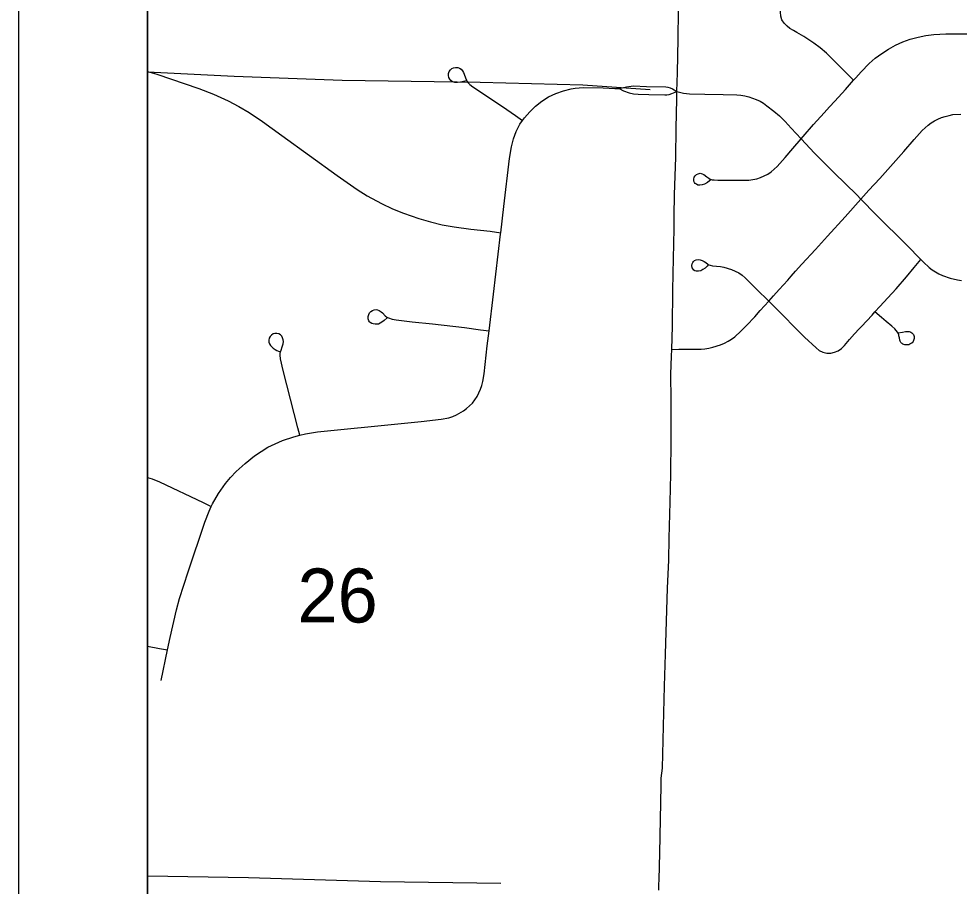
# Model space of a CAD drawing. Extents: x -59 to 43, y 0 to 22.
# Drawn here: x 23.417 to 24.147, y 16.594 to 17.267 of the extents above; entities that cross this region are included whole.
import ezdxf

# ---------------------------------------------------------------- set-up
doc = ezdxf.new("R2010")
doc.units = 0
for name, color, linetype in [('Default', 7, 'Continuous'), ('GM_X_City_Street', 7, 'Continuous'), ('GM_X_Interchange_Ramps', 7, 'Continuous'), ('GM_X_Minor_River', 7, 'Continuous'), ('GM_X_Section_Text', 7, 'Continuous'), ('GM_X_Township_Road', 7, 'Continuous'), ('SH_Data', 7, 'Continuous')]:
    doc.layers.add(name, color=color, linetype=linetype)

msp = doc.modelspace()

# ---------------------------------------------------------------- linework, layer by layer
at = {"layer": 'Default'}
msp.add_lwpolyline([(23.51667, 17.35203), (23.51667, 16.35874), (24.14766, 16.33962), (24.1786, 17.34343), (23.63449, 17.34676)], close=True, dxfattribs=at)
at = {"layer": 'GM_X_City_Street'}
for points in [[(24.0646, 17.21948), (24.05888, 17.22518), (24.04347, 17.24048), (24.03874, 17.24455), (24.03372, 17.24826), (24.02584, 17.25337), (24.02046, 17.25653), (24.01783, 17.25819), (24.01514, 17.25973), (24.01288, 17.26144), (24.01073, 17.26369), (24.00892, 17.26623), (24.008, 17.26917), (24.00777, 17.27228), (24.00828, 17.28166), (24.00876, 17.29728), (24.00945, 17.33483), (24.00959, 17.33796), (24.00997, 17.34632)], [(23.95384, 17.14226), (23.95265, 17.14136), (23.95114, 17.14025), (23.94879, 17.13888), (23.94698, 17.13819), (23.94521, 17.13794), (23.94369, 17.13818), (23.94254, 17.13871), (23.94158, 17.13939), (23.9411, 17.14003), (23.94068, 17.14123), (23.94055, 17.14267), (23.94093, 17.14424), (23.94151, 17.14535), (23.9426, 17.14638), (23.94392, 17.14696), (23.94558, 17.14724), (23.94698, 17.14696), (23.94841, 17.14625), (23.95076, 17.14448), (23.95212, 17.14337), (23.9533, 17.14267), (23.95475, 17.14225), (23.95624, 17.1421), (23.95929, 17.14197), (23.96545, 17.14194), (23.97474, 17.14187), (23.98324, 17.14204), (23.98632, 17.14238), (23.98936, 17.14306), (23.99233, 17.144), (23.9952, 17.1452), (23.99794, 17.14667), (24.00052, 17.1484), (24.0029, 17.15039), (24.00515, 17.15255), (24.01138, 17.1595), (24.01734, 17.16652), (24.0239, 17.17397), (24.02543, 17.1757), (24.03355, 17.18503), (24.04175, 17.19423), (24.04594, 17.19878), (24.0501, 17.20333), (24.05819, 17.21236), (24.0646, 17.21948), (24.06638, 17.22146), (24.07052, 17.22605), (24.0767, 17.23256), (24.07896, 17.23464), (24.08135, 17.23663), (24.08639, 17.24032), (24.09165, 17.24362), (24.09711, 17.24658), (24.10276, 17.24917), (24.10858, 17.25133), (24.11457, 17.25299), (24.12069, 17.25418), (24.12687, 17.25495), (24.13616, 17.25542), (24.1453, 17.25557), (24.15739, 17.25535)], [(23.51667, 17.22635), (23.52379, 17.22406), (23.55627, 17.21303), (23.56784, 17.20854), (23.57913, 17.20339), (23.5874, 17.19913), (23.59541, 17.19442), (23.60573, 17.18754), (23.62086, 17.17658), (23.66385, 17.14561), (23.67916, 17.1348), (23.68713, 17.12984), (23.69811, 17.12382), (23.70659, 17.11978), (23.7153, 17.11624), (23.72713, 17.11213), (23.73615, 17.10951), (23.74531, 17.10741), (23.75457, 17.10583), (23.76755, 17.10403), (23.78237, 17.10226), (23.79066, 17.10114)], [(23.76394, 17.21895), (23.76172, 17.21838), (23.75946, 17.21792), (23.75723, 17.21764), (23.75514, 17.21772), (23.75338, 17.21834), (23.75204, 17.21915), (23.75107, 17.22031), (23.7504, 17.22161), (23.75015, 17.2232), (23.75027, 17.2247), (23.75076, 17.22619), (23.75165, 17.2276), (23.75273, 17.22849), (23.75411, 17.22918), (23.7556, 17.22942), (23.75733, 17.22931), (23.75858, 17.2288), (23.76004, 17.22798), (23.76113, 17.22681), (23.76192, 17.22537), (23.76239, 17.22424), (23.76337, 17.22128), (23.76402, 17.21957), (23.76465, 17.21852), (23.76547, 17.21739), (23.76665, 17.21626), (23.76906, 17.21438), (23.79208, 17.19903), (23.80214, 17.192), (23.80755, 17.18822)], [(23.52713, 16.7537), (23.53214, 16.7774), (23.5342, 16.78719), (23.53894, 16.80845), (23.54143, 16.81744), (23.5482, 16.83814), (23.56092, 16.87655), (23.56433, 16.88523), (23.56602, 16.88874), (23.56703, 16.89083), (23.57176, 16.89887), (23.57713, 16.90651), (23.58108, 16.91133), (23.58535, 16.91586), (23.59222, 16.92217), (23.59953, 16.92797), (23.60467, 16.93149), (23.61002, 16.93466), (23.61559, 16.93744), (23.62133, 16.93985), (23.63016, 16.94286), (23.63472, 16.944), (23.63921, 16.94512), (23.64841, 16.9467), (23.66389, 16.94829), (23.69795, 16.9517), (23.72893, 16.95465), (23.7444, 16.95641), (23.7505, 16.95762), (23.75345, 16.95858), (23.75629, 16.95984), (23.76172, 16.96289), (23.76424, 16.96471), (23.76658, 16.96676), (23.76873, 16.96902), (23.77065, 16.97146), (23.77234, 16.97407), (23.7738, 16.97682), (23.77501, 16.97968), (23.77599, 16.98264), (23.77675, 16.98565), (23.77778, 16.99179), (23.78025, 17.01343), (23.7816, 17.02497), (23.78498, 17.05361), (23.79052, 17.09996), (23.79066, 17.10114), (23.79317, 17.12158), (23.79753, 17.15867), (23.79904, 17.16788), (23.80058, 17.17391), (23.8028, 17.17973), (23.80562, 17.18527), (23.80755, 17.18822), (23.80916, 17.19037), (23.81324, 17.19507), (23.81769, 17.19942), (23.8226, 17.20325), (23.82787, 17.20655), (23.83348, 17.20925), (23.83935, 17.21132), (23.84538, 17.21285), (23.84845, 17.21334), (23.85466, 17.21374), (23.87021, 17.21349), (23.87922, 17.2131), (23.88265, 17.21295)], [(23.88265, 17.21295), (23.88823, 17.21437), (23.89382, 17.21503), (23.90384, 17.21472), (23.91889, 17.21424), (23.92045, 17.21408), (23.92213, 17.2137), (23.92397, 17.21285), (23.92747, 17.21066)], [(23.88265, 17.21295), (23.88593, 17.21133), (23.89048, 17.20972), (23.89385, 17.20902), (23.89734, 17.20855), (23.90574, 17.20853), (23.91809, 17.20817), (23.91969, 17.20825), (23.92152, 17.20852), (23.92348, 17.20907), (23.92747, 17.21066)], [(23.92747, 17.21066), (23.93262, 17.20944), (23.93495, 17.20913), (23.93724, 17.20896), (23.94918, 17.20868), (23.96335, 17.20835), (23.97392, 17.20809), (23.97707, 17.20782), (23.9802, 17.20733), (23.98324, 17.20662), (23.98905, 17.20453), (23.99197, 17.20321), (23.99474, 17.2016), (23.99733, 17.19972), (24.00268, 17.19535), (24.0071, 17.19176), (24.01141, 17.18733), (24.01621, 17.18219), (24.0239, 17.17397), (24.03422, 17.16291), (24.04951, 17.14773), (24.06701, 17.13065), (24.07023, 17.12731), (24.08206, 17.11504), (24.10584, 17.09139), (24.11679, 17.08038), (24.1188, 17.07836), (24.12324, 17.07419), (24.12564, 17.07237), (24.12817, 17.07073), (24.13081, 17.06914), (24.13363, 17.06802), (24.13939, 17.06597), (24.14533, 17.0645), (24.14833, 17.06405)], [(23.92342, 17.01065), (23.92889, 17.0107), (23.93655, 17.01078), (23.94282, 17.01074), (23.94636, 17.01092), (23.94911, 17.01115), (23.95223, 17.01165), (23.95532, 17.01234), (23.96136, 17.01427), (23.96427, 17.01551), (23.9671, 17.01697), (23.96981, 17.01862), (23.97237, 17.02049), (23.9771, 17.02468), (23.98145, 17.02917), (23.98786, 17.03597), (23.99198, 17.04069), (23.99877, 17.04815), (24.00247, 17.05223), (24.0068, 17.05699), (24.01024, 17.06077), (24.01354, 17.06441), (24.01622, 17.06736), (24.01945, 17.07124), (24.02443, 17.07671), (24.03492, 17.08822), (24.04432, 17.09855), (24.05792, 17.1135), (24.07023, 17.12731), (24.07642, 17.13426), (24.08482, 17.14333), (24.09742, 17.15708), (24.10358, 17.16409), (24.11165, 17.17354), (24.11786, 17.18041), (24.12239, 17.18452), (24.12481, 17.18634), (24.12736, 17.18795), (24.13004, 17.18933), (24.13284, 17.19046), (24.13573, 17.19145), (24.13866, 17.19224), (24.14164, 17.19278), (24.14773, 17.19325)], [(23.95174, 17.07634), (23.95087, 17.0751), (23.9494, 17.07362), (23.94763, 17.07251), (23.94594, 17.07168), (23.94416, 17.07124), (23.94245, 17.07135), (23.94146, 17.07165), (23.94063, 17.07214), (23.94001, 17.07279), (23.93937, 17.07404), (23.93911, 17.07564), (23.93935, 17.07709), (23.93969, 17.07798), (23.94022, 17.07873), (23.94109, 17.07954), (23.94244, 17.08013), (23.9439, 17.08039), (23.94554, 17.08018), (23.94713, 17.07962), (23.94861, 17.07884), (23.94993, 17.07794), (23.95145, 17.07687), (23.95232, 17.07634), (23.9533, 17.07601), (23.95516, 17.07557), (23.96117, 17.07491), (23.96398, 17.07432), (23.96975, 17.07256), (23.97268, 17.07145), (23.97544, 17.07002), (23.97799, 17.06827), (23.98033, 17.06622), (23.98915, 17.05748), (23.99877, 17.04815), (24.0025, 17.04454), (24.02642, 17.02022), (24.03554, 17.01176), (24.03797, 17.00986), (24.04069, 17.00845), (24.04371, 17.00773), (24.04681, 17.00771), (24.04985, 17.00836), (24.05268, 17.0096), (24.05521, 17.01137), (24.05738, 17.01357), (24.0615, 17.01825), (24.06536, 17.02265), (24.06892, 17.02654), (24.07072, 17.02852), (24.07478, 17.0329), (24.07885, 17.03732), (24.08108, 17.03978), (24.0849, 17.04398), (24.09119, 17.05074), (24.0975, 17.0576), (24.10571, 17.0669), (24.1116, 17.07408), (24.11679, 17.08038)], [(23.70246, 17.0351), (23.70032, 17.03312), (23.69851, 17.03172), (23.69715, 17.03094), (23.69575, 17.03032), (23.6946, 17.03011), (23.69326, 17.03013), (23.6918, 17.03034), (23.69058, 17.03065), (23.6893, 17.03143), (23.68881, 17.03192), (23.6882, 17.03279), (23.68782, 17.03432), (23.68782, 17.03604), (23.68826, 17.03771), (23.68896, 17.03909), (23.68982, 17.04004), (23.69106, 17.0409), (23.69249, 17.04138), (23.69392, 17.04147), (23.69497, 17.04128), (23.69628, 17.0408), (23.69781, 17.03986), (23.69882, 17.03901), (23.70108, 17.0368), (23.70238, 17.03567), (23.70362, 17.03502), (23.70655, 17.03405), (23.70962, 17.03356), (23.72207, 17.0321), (23.73764, 17.03036), (23.76253, 17.0276), (23.77493, 17.02589), (23.7816, 17.02497)], [(24.09923, 17.02337), (24.1024, 17.02401), (24.10497, 17.02447), (24.10586, 17.02454), (24.10653, 17.02453), (24.10757, 17.0244), (24.10847, 17.02415), (24.10905, 17.02388), (24.10965, 17.02351), (24.11039, 17.02291), (24.11093, 17.02223), (24.11128, 17.02147), (24.11151, 17.02062), (24.11162, 17.01981), (24.11154, 17.01896), (24.11136, 17.01822), (24.11118, 17.01755), (24.11083, 17.01684), (24.11, 17.01582), (24.10939, 17.01536), (24.10874, 17.01491), (24.10808, 17.01457), (24.10739, 17.01429), (24.10657, 17.01413), (24.10577, 17.01409), (24.10499, 17.01413), (24.10425, 17.01429), (24.10347, 17.01452), (24.10286, 17.01477), (24.1023, 17.01513), (24.10176, 17.01556), (24.10125, 17.01611), (24.10079, 17.0169), (24.10053, 17.01767), (24.10007, 17.01953), (24.09979, 17.02109), (24.09962, 17.02188), (24.09912, 17.02313), (24.09853, 17.02408), (24.09651, 17.02652), (24.09422, 17.02864), (24.08987, 17.03233), (24.08631, 17.03534), (24.08108, 17.03978)], [(23.63472, 16.944), (23.63324, 16.9498), (23.6219, 16.9943), (23.61982, 17.00321), (23.61952, 17.00624), (23.61964, 17.008), (23.62022, 17.01014), (23.62116, 17.01257), (23.62193, 17.01505), (23.62206, 17.01665), (23.62194, 17.01804), (23.62142, 17.0197), (23.62072, 17.02079), (23.61972, 17.02194), (23.61835, 17.02269), (23.61689, 17.02305), (23.61541, 17.02305), (23.61408, 17.02261), (23.61271, 17.02178), (23.6117, 17.0207), (23.61099, 17.01928), (23.61072, 17.01785), (23.61073, 17.01628), (23.6112, 17.01487), (23.612, 17.01355), (23.61401, 17.0117), (23.61553, 17.01063), (23.61701, 17.00984), (23.61829, 17.00931), (23.6196, 17.00894)], [(23.51667, 16.91115), (23.52008, 16.91026), (23.52588, 16.90796), (23.55967, 16.89178), (23.56602, 16.88874)], [(23.51667, 16.78038), (23.5259, 16.7786), (23.53214, 16.7774)]]:
    msp.add_lwpolyline(points, dxfattribs=at)
at = {"layer": 'GM_X_Interchange_Ramps'}
msp.add_lwpolyline([(23.51667, 20.9), (23.51667, 15.35309)], dxfattribs=at)
at = {"layer": 'GM_X_Minor_River'}
for points in [[(23.51667, 17.22598), (23.58386, 17.22273), (23.6677, 17.21944), (23.77469, 17.21797), (23.85437, 17.21583), (23.90672, 17.21225)], [(23.51667, 16.60227), (23.59488, 16.60078), (23.69732, 16.59781), (23.79065, 16.59638)]]:
    msp.add_lwpolyline(points, dxfattribs=at)
at = {"layer": 'GM_X_Township_Road'}
for points in [[(23.92747, 17.21066), (23.92781, 17.22522), (23.92846, 17.25171), (23.92877, 17.27326), (23.9291, 17.28922), (23.92926, 17.29974), (23.92946, 17.33132), (23.92977, 17.34602)], [(23.92342, 17.01065), (23.92393, 17.02869), (23.92427, 17.05664), (23.92469, 17.08146), (23.92496, 17.09233), (23.92522, 17.10474), (23.92533, 17.11407), (23.92555, 17.1308), (23.92652, 17.15943), (23.92685, 17.18229), (23.92732, 17.20466), (23.92747, 17.21066)], [(23.91524, 16.67231), (23.91526, 16.6733), (23.91534, 16.67785), (23.91628, 16.68574), (23.917, 16.71832), (23.91792, 16.74935), (23.91865, 16.77418), (23.91905, 16.79125), (23.92015, 16.82537), (23.92114, 16.84709), (23.92155, 16.86418), (23.92211, 16.8921), (23.9226, 16.91383), (23.92298, 16.94023), (23.92296, 16.94501), (23.92291, 16.95423), (23.92293, 16.95626), (23.923, 16.97128), (23.9228, 16.99146), (23.92327, 17.0054), (23.92342, 17.01065)], [(23.91328, 16.59094), (23.91346, 16.59512), (23.91363, 16.59929), (23.91424, 16.61969), (23.91524, 16.67231)]]:
    msp.add_lwpolyline(points, dxfattribs=at)
at = {"layer": 'SH_Data'}
for points in [[(23.41667, 21), (30.41667, 21), (30.41667, 14), (23.41667, 14)], [(23.51667, 20.9), (30.31667, 20.9), (30.31667, 14.1), (23.51667, 14.1)]]:
    msp.add_lwpolyline(points, close=True, dxfattribs=at)

# ---------------------------------------------------------------- texts
at = {"layer": 'GM_X_Section_Text'}
msp.add_text('26', height=0.041856, rotation=0.00001, dxfattribs=at).set_placement((23.63297, 16.79874))

doc.saveas('drawing.dxf')
